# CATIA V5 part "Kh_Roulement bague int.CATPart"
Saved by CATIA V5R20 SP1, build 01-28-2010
Part number: Roulement bague int
Bounding box of the stored display mesh (mm): x -12.495 to 12.495, y -12.495 to 12.495, z -10 to 2
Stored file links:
  G:\Khaled_CFAO_2011\SIL\SIL_GR1\tmerino\Khaled\CAD_Thinkmotion\Kh_Roulement bague int.CATPart
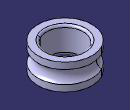
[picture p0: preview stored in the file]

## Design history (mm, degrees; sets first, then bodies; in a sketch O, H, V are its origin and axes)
Body1 (main body)
  Sketch1 on yz-plane, origin (0, 0, 0), H (0, 1, 0), V (0, 0, 1)
    line L1 (8.5, -10) -> (8.5, 2)
    line L2 (8.5, 2) -> (12.5, 2)
    line L3 (8.5, -10) -> (12.5, -10)
    line L4 (12.5, 2) -> (12.5, -1)
    line L5 (12.5, -10) -> (12.5, -7)
    arc A1 centre (14.25, -4) radius 3.4731 from (12.5, -1) to (12.5, -7) ccw
    distance L1 V = 8.5
    length L2 = 4
    length L3 = 4
    length L1 = 12
    length L4 = 3
    length L5 = 3
    vertical: L1 V, L4 V, L5 V
    horizontal: L2 H, L3 H
  Shaft1: profile Sketch1, axis Sketch1.V, angle 360
  Fillet1: radius 1, on face of Shaft1 from Sketch1.L1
